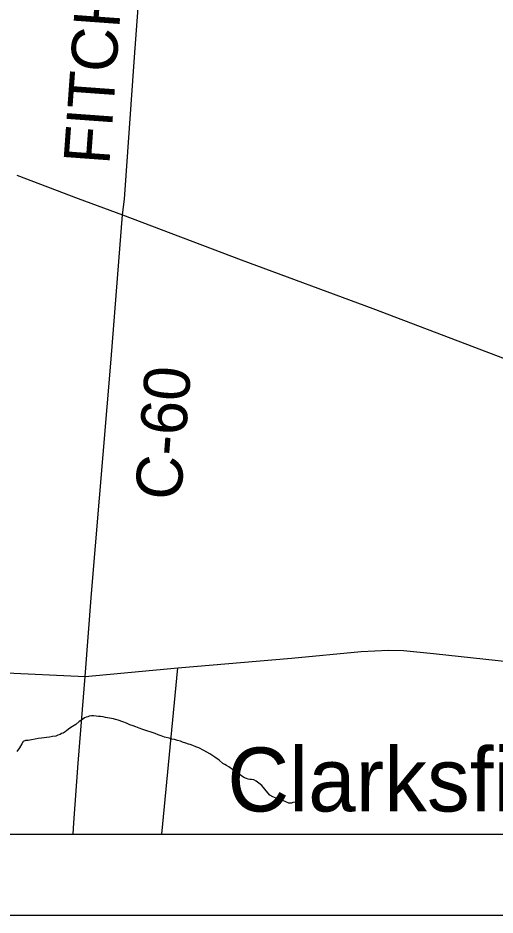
# Model space of a CAD drawing. Extents: x 0 to 34, y 0 to 22.
# Drawn here: x 2.447 to 3.036, y 14 to 15.108 of the extents above; entities that cross this region are included whole.
import ezdxf

# ---------------------------------------------------------------- set-up
doc = ezdxf.new("R2010")
doc.units = 0
for name, color, linetype in [('GM_X_Corporation', 7, 'Continuous'), ('GM_X_County_Road', 7, 'Continuous'), ('GM_X_County_Road_Text', 7, 'Continuous'), ('GM_X_Minor_River', 7, 'Continuous'), ('GM_X_State_Route', 7, 'Continuous'), ('GM_X_Township_Road', 7, 'Continuous'), ('GM_X_Unincorporated_Text', 7, 'Continuous'), ('SH_Data', 7, 'Continuous')]:
    doc.layers.add(name, color=color, linetype=linetype)

msp = doc.modelspace()

# ---------------------------------------------------------------- linework, layer by layer
at = {"layer": 'GM_X_Corporation'}
msp.add_lwpolyline([(2.1, 20.3879), (2.1, 14.1), (7.1335, 14.1), (7.1269, 14.4049), (7.1267, 14.4123), (7.1215, 14.6514), (7.118, 14.8105), (7.1072, 15.3824), (7.0838, 16.6084)], dxfattribs=at)
msp.add_lwpolyline([(2.1, 15.3574), (2.1, 14.1), (7.1335, 14.1), (7.1269, 14.4049), (7.1267, 14.4123), (7.1215, 14.6514), (7.118, 14.8105), (7.1072, 15.3824), (6.0415, 15.3685), (5.8313, 15.3671), (5.1944, 15.3696), (4.1554, 15.3654), (4.1534, 15.3654), (3.4135, 15.3624), (2.6127, 15.3592)], close=True, dxfattribs=at)
at = {"layer": 'GM_X_County_Road'}
for points in [[(2.5151, 14.1), (2.5162, 14.1138), (2.5215, 14.1876), (2.5299, 14.2946), (2.538, 14.3971), (2.5621, 14.6864), (2.5763, 14.8647), (2.5787, 14.884), (2.5909, 15.0595), (2.6111, 15.3314), (2.6113, 15.3344), (2.6114, 15.3353)], [(2.5299, 14.2946), (2.6445, 14.3054), (2.785, 14.3173), (2.8709, 14.3255), (2.9046, 14.3272), (2.9231, 14.3268), (2.96, 14.3231), (3.055, 14.3128), (3.1618, 14.3017), (3.26, 14.2914), (3.3683, 14.28), (3.4271, 14.276)], [(2.1, 14.3107), (2.122, 14.3108), (2.1603, 14.3107), (2.2123, 14.3096), (2.5299, 14.2946)]]:
    msp.add_lwpolyline(points, dxfattribs=at)
at = {"layer": 'GM_X_Minor_River'}
msp.add_lwpolyline([(2.7893, 14.1396), (2.7866, 14.1389), (2.7847, 14.1381), (2.7816, 14.1382), (2.7779, 14.1397), (2.7741, 14.1413), (2.7699, 14.1429), (2.7658, 14.1444), (2.7616, 14.146), (2.7582, 14.1479), (2.7556, 14.151), (2.7518, 14.1556), (2.7481, 14.1598), (2.7443, 14.1629), (2.7413, 14.1652), (2.7383, 14.1668), (2.7356, 14.1672), (2.7333, 14.1676), (2.7311, 14.168), (2.7292, 14.1688), (2.7269, 14.1696), (2.7246, 14.1708), (2.7216, 14.1731), (2.7118, 14.1797), (2.7073, 14.1831), (2.7047, 14.1847), (2.7024, 14.1859), (2.7001, 14.187), (2.6956, 14.1913), (2.69, 14.1951), (2.6839, 14.199), (2.6764, 14.2033), (2.6703, 14.2064), (2.6669, 14.2076), (2.6628, 14.2095), (2.6597, 14.2107), (2.6575, 14.2111), (2.6544, 14.2123), (2.6503, 14.2135), (2.6476, 14.2146), (2.6442, 14.2154), (2.6404, 14.2166), (2.637, 14.2174), (2.6336, 14.2186), (2.6302, 14.2194), (2.6279, 14.2198), (2.6241, 14.2214), (2.6203, 14.2225), (2.6166, 14.2241), (2.6116, 14.2257), (2.606, 14.2277), (2.6014, 14.2292), (2.5969, 14.2308), (2.5927, 14.2324), (2.5893, 14.2336), (2.5851, 14.2351), (2.581, 14.2371), (2.5764, 14.2387), (2.5708, 14.2406), (2.5677, 14.2414), (2.5651, 14.2422), (2.5552, 14.2438), (2.5522, 14.2446), (2.5491, 14.2451), (2.5465, 14.2451), (2.5438, 14.2455), (2.5404, 14.2459), (2.5378, 14.246), (2.5351, 14.2456), (2.5332, 14.2449), (2.5313, 14.2445), (2.5294, 14.2434), (2.5267, 14.2415), (2.5228, 14.2389), (2.5186, 14.2355), (2.5144, 14.2329), (2.511, 14.2307), (2.5075, 14.2281), (2.5052, 14.2262), (2.5029, 14.2247), (2.501, 14.224), (2.4991, 14.2228), (2.4964, 14.2221), (2.4937, 14.221), (2.4899, 14.2203), (2.4861, 14.2196), (2.4823, 14.2192), (2.4793, 14.2189), (2.4762, 14.2186), (2.472, 14.2182), (2.4682, 14.2171), (2.4637, 14.2164), (2.4595, 14.2157), (2.4564, 14.2154), (2.4534, 14.2143), (2.4518, 14.2116), (2.4491, 14.2063), (2.4456, 14.2018)], dxfattribs=at)
at = {"layer": 'GM_X_State_Route'}
msp.add_lwpolyline([(2.4458, 14.9138), (2.5214, 14.8849), (2.5763, 14.8647), (2.7228, 14.8093), (2.8854, 14.7492), (3.133, 14.6548), (3.2349, 14.6177), (3.2677, 14.6047), (3.3003, 14.5887), (3.3254, 14.5731), (3.3439, 14.5572), (3.3597, 14.5418), (3.3755, 14.5231), (3.3889, 14.5033), (3.3994, 14.4847), (3.4129, 14.4521), (3.4195, 14.4267), (3.4245, 14.3909), (3.4256, 14.344), (3.4271, 14.276)], dxfattribs=at)
at = {"layer": 'GM_X_Township_Road'}
msp.add_line((2.6248, 14.1), (2.6445, 14.3054), dxfattribs=at)
at = {"layer": 'SH_Data'}
for p, q in [((2.1, 14.1), (8.9, 14.1)), ((2, 14), (9, 14))]:
    msp.add_line(p, q, dxfattribs=at)

# ---------------------------------------------------------------- texts
at = {"layer": 'GM_X_County_Road_Text'}
for s, rotation, p in [('FITCHVILLE', 85.8383, (2.5599, 14.9258)), ('C-60', 85.5486, (2.6481, 14.5111))]:
    msp.add_text(s, height=0.05682, rotation=rotation, dxfattribs=at).set_placement(p)
at = {"layer": 'GM_X_Unincorporated_Text'}
msp.add_text('Clarksfield', height=0.078977, rotation=0, dxfattribs=at).set_placement((2.7056, 14.1279))

doc.saveas('drawing.dxf')
